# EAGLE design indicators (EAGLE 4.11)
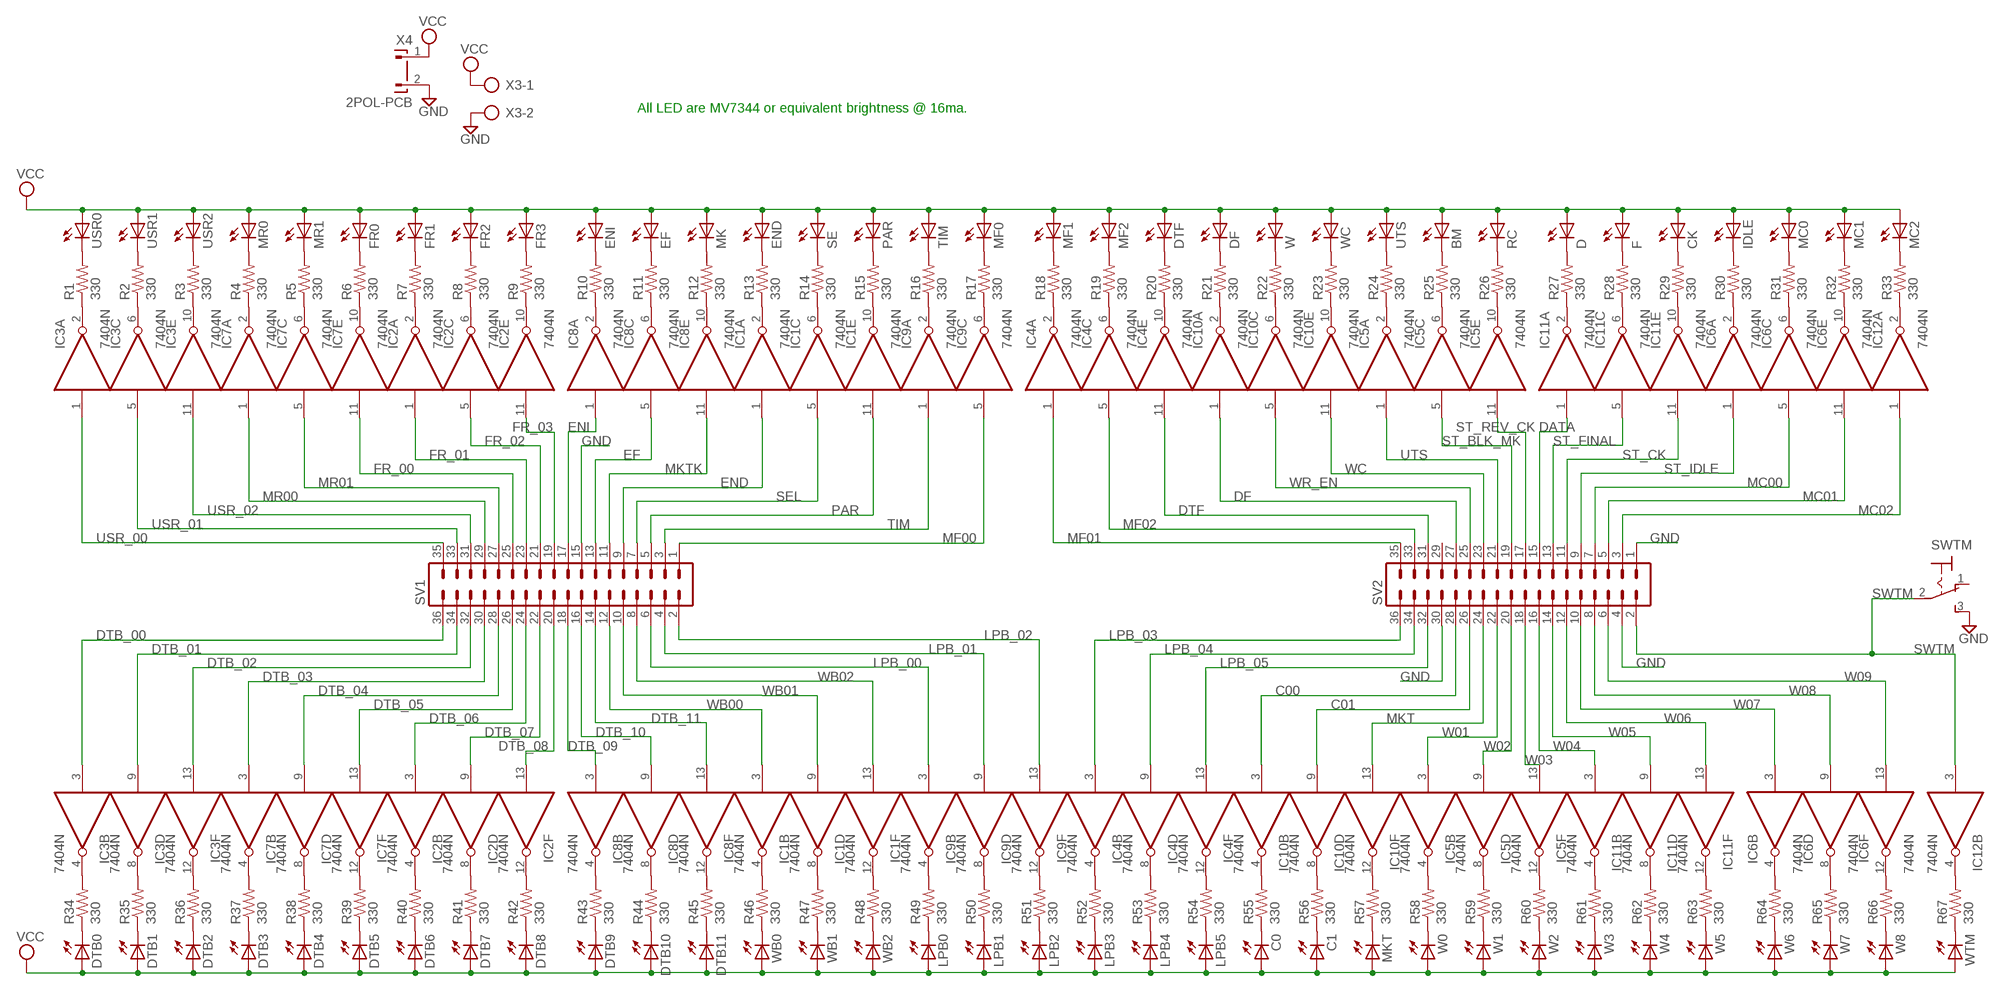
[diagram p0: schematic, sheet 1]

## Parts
BM  LED5MM  [LED5MM]
C0  LED5MM  [LED5MM]
C1  LED5MM  [LED5MM]
CK  LED5MM  [LED5MM]
D  LED5MM  [LED5MM]
DF  LED5MM  [LED5MM]
DTB0  LED5MM  [LED5MM]
DTB1  LED5MM  [LED5MM]
DTB2  LED5MM  [LED5MM]
DTB3  LED5MM  [LED5MM]
DTB4  LED5MM  [LED5MM]
DTB5  LED5MM  [LED5MM]
DTB6  LED5MM  [LED5MM]
DTB7  LED5MM  [LED5MM]
DTB8  LED5MM  [LED5MM]
DTB9  LED5MM  [LED5MM]
DTB10  LED5MM  [LED5MM]
DTB11  LED5MM  [LED5MM]
DTF  LED5MM  [LED5MM]
EF  LED5MM  [LED5MM]
END  LED5MM  [LED5MM]
ENI  LED5MM  [LED5MM]
F  LED5MM  [LED5MM]
FR0  LED5MM  [LED5MM]
FR1  LED5MM  [LED5MM]
FR2  LED5MM  [LED5MM]
FR3  LED5MM  [LED5MM]
IC1  7404N  [DIL14]
IC2  7404N  [DIL14]
IC3  7404N  [DIL14]
IC4  7404N  [DIL14]
IC5  7404N  [DIL14]
IC6  7404N  [DIL14]
IC7  7404N  [DIL14]
IC8  7404N  [DIL14]
IC9  7404N  [DIL14]
IC10  7404N  [DIL14]
IC11  7404N  [DIL14]
IC12  7404N  [DIL14]
IDLE  LED5MM  [LED5MM]
LPB0  LED5MM  [LED5MM]
LPB1  LED5MM  [LED5MM]
LPB2  LED5MM  [LED5MM]
LPB3  LED5MM  [LED5MM]
LPB4  LED5MM  [LED5MM]
LPB5  LED5MM  [LED5MM]
MC0  LED5MM  [LED5MM]
MC1  LED5MM  [LED5MM]
MC2  LED5MM  [LED5MM]
MF0  LED5MM  [LED5MM]
MF1  LED5MM  [LED5MM]
MF2  LED5MM  [LED5MM]
MK  LED5MM  [LED5MM]
MKT  LED5MM  [LED5MM]
MR0  LED5MM  [LED5MM]
MR1  LED5MM  [LED5MM]
PAR  LED5MM  [LED5MM]
R1  330  R-US_0207/10  [0207/10]
R2  330  R-US_0207/10  [0207/10]
R3  330  R-US_0207/10  [0207/10]
R4  330  R-US_0207/10  [0207/10]
R5  330  R-US_0207/10  [0207/10]
R6  330  R-US_0207/10  [0207/10]
R7  330  R-US_0207/10  [0207/10]
R8  330  R-US_0207/10  [0207/10]
R9  330  R-US_0207/10  [0207/10]
R10  330  R-US_0207/10  [0207/10]
R11  330  R-US_0207/10  [0207/10]
R12  330  R-US_0207/10  [0207/10]
R13  330  R-US_0207/10  [0207/10]
R14  330  R-US_0207/10  [0207/10]
R15  330  R-US_0207/10  [0207/10]
R16  330  R-US_0207/10  [0207/10]
R17  330  R-US_0207/10  [0207/10]
R18  330  R-US_0207/10  [0207/10]
R19  330  R-US_0207/10  [0207/10]
R20  330  R-US_0207/10  [0207/10]
R21  330  R-US_0207/10  [0207/10]
R22  330  R-US_0207/10  [0207/10]
R23  330  R-US_0207/10  [0207/10]
R24  330  R-US_0207/10  [0207/10]
R25  330  R-US_0207/10  [0207/10]
R26  330  R-US_0207/10  [0207/10]
R27  330  R-US_0207/10  [0207/10]
R28  330  R-US_0207/10  [0207/10]
R29  330  R-US_0207/10  [0207/10]
R30  330  R-US_0207/10  [0207/10]
R31  330  R-US_0207/10  [0207/10]
R32  330  R-US_0207/10  [0207/10]
R33  330  R-US_0207/10  [0207/10]
R34  330  R-US_0207/10  [0207/10]
R35  330  R-US_0207/10  [0207/10]
R36  330  R-US_0207/10  [0207/10]
R37  330  R-US_0207/10  [0207/10]
R38  330  R-US_0207/10  [0207/10]
R39  330  R-US_0207/10  [0207/10]
R40  330  R-US_0207/10  [0207/10]
R41  330  R-US_0207/10  [0207/10]
R42  330  R-US_0207/10  [0207/10]
R43  330  R-US_0207/10  [0207/10]
R44  330  R-US_0207/10  [0207/10]
R45  330  R-US_0207/10  [0207/10]
R46  330  R-US_0207/10  [0207/10]
R47  330  R-US_0207/10  [0207/10]
R48  330  R-US_0207/10  [0207/10]
R49  330  R-US_0207/10  [0207/10]
R50  330  R-US_0207/10  [0207/10]
R51  330  R-US_0207/10  [0207/10]
R52  330  R-US_0207/10  [0207/10]
R53  330  R-US_0207/10  [0207/10]
R54  330  R-US_0207/10  [0207/10]
R55  330  R-US_0207/10  [0207/10]
R56  330  R-US_0207/10  [0207/10]
R57  330  R-US_0207/10  [0207/10]
R58  330  R-US_0207/10  [0207/10]
R59  330  R-US_0207/10  [0207/10]
R60  330  R-US_0207/10  [0207/10]
R61  330  R-US_0207/10  [0207/10]
R62  330  R-US_0207/10  [0207/10]
R63  330  R-US_0207/10  [0207/10]
R64  330  R-US_0207/10  [0207/10]
R65  330  R-US_0207/10  [0207/10]
R66  330  R-US_0207/10  [0207/10]
R67  330  R-US_0207/10  [0207/10]
RC  LED5MM  [LED5MM]
SE  LED5MM  [LED5MM]
SV1  MA18-2  [MA18-2]
SV2  MA18-2  [MA18-2]
SWTM  M9040P  [M9040P]
TIM  LED5MM  [LED5MM]
USR0  LED5MM  [LED5MM]
USR1  LED5MM  [LED5MM]
USR2  LED5MM  [LED5MM]
UTS  LED5MM  [LED5MM]
W  LED5MM  [LED5MM]
W0  LED5MM  [LED5MM]
W1  LED5MM  [LED5MM]
W2  LED5MM  [LED5MM]
W3  LED5MM  [LED5MM]
W4  LED5MM  [LED5MM]
W5  LED5MM  [LED5MM]
W6  LED5MM  [LED5MM]
W7  LED5MM  [LED5MM]
W8  LED5MM  [LED5MM]
WB0  LED5MM  [LED5MM]
WB1  LED5MM  [LED5MM]
WB2  LED5MM  [LED5MM]
WC  LED5MM  [LED5MM]
WTM  LED5MM  [LED5MM]
X3  AK300/2  [AK300/2]
X4  2POL-PCB  [2POL-PCB]

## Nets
C00: IC10.3(B:I) SV2.28
C01: IC10.9(D:I) SV2.26
DATA: IC11.1(A:I) SV2.15
DF: IC10.1(A:I) SV2.27
DTB_00: IC3.3(B:I) SV1.36
DTB_01: IC3.9(D:I) SV1.34
DTB_02: IC3.13(F:I) SV1.32
DTB_03: IC7.3(B:I) SV1.30
DTB_04: IC7.9(D:I) SV1.28
DTB_05: IC7.13(F:I) SV1.26
DTB_06: IC2.3(B:I) SV1.24
DTB_07: IC2.9(D:I) SV1.22
DTB_08: IC2.13(F:I) SV1.20
DTB_09: IC8.3(B:I) SV1.18
DTB_10: IC8.9(D:I) SV1.16
DTB_11: IC8.13(F:I) SV1.14
DTF: IC4.11(E:I) SV2.31
EF: IC8.5(C:I) SV1.13
END: IC1.1(A:I) SV1.9
ENI: IC8.1(A:I) SV1.17
FR_00: IC7.11(E:I) SV1.25
FR_01: IC2.1(A:I) SV1.23
FR_02: IC2.5(C:I) SV1.21
FR_03: IC2.11(E:I) SV1.19
GND: SV1.15 SV2.1 SV2.4 SV2.30 SWTM.3(S) X3.2 X4.2
LPB_00: IC9.3(B:I) SV1.6
LPB_01: IC9.9(D:I) SV1.4
LPB_02: IC9.13(F:I) SV1.2
LPB_03: IC4.3(B:I) SV2.36
LPB_04: IC4.9(D:I) SV2.34
LPB_05: IC4.13(F:I) SV2.32
MC00: IC6.5(C:I) SV2.7
MC01: IC6.11(E:I) SV2.5
MC02: IC12.1(A:I) SV2.3
MF00: IC9.5(C:I) SV1.1
MF01: IC4.1(A:I) SV2.35
MF02: IC4.5(C:I) SV2.33
MKT: IC10.13(F:I) SV2.24
MKTK: IC8.11(E:I) SV1.11
MR00: IC7.1(A:I) SV1.29
MR01: IC7.5(C:I) SV1.27
N$1: R1.2 USR0.K(C)
N$2: R2.2 USR1.K(C)
N$3: R3.2 USR2.K(C)
N$4: MR0.K(C) R4.2
N$5: MR1.K(C) R5.2
N$6: FR0.K(C) R6.2
N$7: FR1.K(C) R7.2
N$8: FR2.K(C) R8.2
N$9: FR3.K(C) R9.2
N$10: ENI.K(C) R10.2
N$11: EF.K(C) R11.2
N$12: MK.K(C) R12.2
N$13: END.K(C) R13.2
N$14: R14.2 SE.K(C)
N$15: PAR.K(C) R15.2
N$16: R16.2 TIM.K(C)
N$17: MF0.K(C) R17.2
N$18: MF1.K(C) R18.2
N$19: MF2.K(C) R19.2
N$20: IC3.2(A:O) R1.1
N$21: IC3.6(C:O) R2.1
N$22: IC3.10(E:O) R3.1
N$23: IC7.2(A:O) R4.1
N$24: IC7.6(C:O) R5.1
N$25: IC7.10(E:O) R6.1
N$26: IC2.2(A:O) R7.1
N$27: IC2.6(C:O) R8.1
N$28: IC2.10(E:O) R9.1
N$29: IC8.2(A:O) R10.1
N$30: IC8.6(C:O) R11.1
N$31: IC8.10(E:O) R12.1
N$32: IC1.2(A:O) R13.1
N$33: IC1.6(C:O) R14.1
N$34: IC1.10(E:O) R15.1
N$35: IC9.2(A:O) R16.1
N$36: IC9.6(C:O) R17.1
N$37: IC4.2(A:O) R18.1
N$38: DTF.K(C) R20.2
N$57: DF.K(C) R21.2
N$58: R22.2 W.K(C)
N$59: R23.2 WC.K(C)
N$60: R24.2 UTS.K(C)
N$61: BM.K(C) R25.2
N$62: R26.2 RC.K(C)
N$63: D.K(C) R27.2
N$64: F.K(C) R28.2
N$65: CK.K(C) R29.2
N$66: IDLE.K(C) R30.2
N$67: MC0.K(C) R31.2
N$68: MC1.K(C) R32.2
N$69: MC2.K(C) R33.2
N$70: IC4.6(C:O) R19.1
N$71: IC4.10(E:O) R20.1
N$72: IC10.2(A:O) R21.1
N$73: IC10.10(E:O) R23.1
N$74: IC10.6(C:O) R22.1
N$75: IC5.2(A:O) R24.1
N$76: IC5.6(C:O) R25.1
N$77: IC5.10(E:O) R26.1
N$78: IC11.2(A:O) R27.1
N$79: IC11.6(C:O) R28.1
N$80: IC11.10(E:O) R29.1
N$81: IC6.2(A:O) R30.1
N$82: IC6.6(C:O) R31.1
N$83: IC6.10(E:O) R32.1
N$84: IC12.2(A:O) R33.1
N$89: DTB0.K(C) R34.1
N$90: DTB1.K(C) R35.1
N$91: DTB2.K(C) R36.1
N$92: DTB3.K(C) R37.1
N$93: DTB4.K(C) R38.1
N$94: DTB5.K(C) R39.1
N$95: DTB6.K(C) R40.1
N$96: DTB7.K(C) R41.1
N$97: DTB8.K(C) R42.1
N$98: DTB9.K(C) R43.1
N$99: DTB10.K(C) R44.1
N$100: DTB11.K(C) R45.1
N$101: R46.1 WB0.K(C)
N$102: R47.1 WB1.K(C)
N$103: R48.1 WB2.K(C)
N$104: LPB0.K(C) R49.1
N$105: LPB1.K(C) R50.1
N$106: LPB2.K(C) R51.1
N$107: LPB3.K(C) R52.1
N$108: LPB4.K(C) R53.1
N$109: LPB5.K(C) R54.1
N$110: C0.K(C) R55.1
N$111: C1.K(C) R56.1
N$112: MKT.K(C) R57.1
N$113: R58.1 W0.K(C)
N$114: R59.1 W1.K(C)
N$115: R60.1 W2.K(C)
N$116: R61.1 W3.K(C)
N$117: R62.1 W4.K(C)
N$118: R63.1 W5.K(C)
N$119: R64.1 W6.K(C)
N$120: R65.1 W7.K(C)
N$121: R66.1 W8.K(C)
N$122: R67.1 WTM.K(C)
N$123: IC3.4(B:O) R34.2
N$124: IC3.8(D:O) R35.2
N$125: IC3.12(F:O) R36.2
N$126: IC7.4(B:O) R37.2
N$127: IC7.8(D:O) R38.2
N$128: IC7.12(F:O) R39.2
N$129: IC2.4(B:O) R40.2
N$130: IC2.8(D:O) R41.2
N$131: IC2.12(F:O) R42.2
N$132: IC8.4(B:O) R43.2
N$133: IC8.8(D:O) R44.2
N$134: IC8.12(F:O) R45.2
N$135: IC1.4(B:O) R46.2
N$136: IC1.8(D:O) R47.2
N$137: IC1.12(F:O) R48.2
N$138: IC9.4(B:O) R49.2
N$139: IC9.8(D:O) R50.2
N$140: IC9.12(F:O) R51.2
N$141: IC4.4(B:O) R52.2
N$142: IC4.8(D:O) R53.2
N$143: IC4.12(F:O) R54.2
N$144: IC10.4(B:O) R55.2
N$145: IC10.8(D:O) R56.2
N$146: IC10.12(F:O) R57.2
N$147: IC5.4(B:O) R58.2
N$148: IC5.8(D:O) R59.2
N$149: IC5.12(F:O) R60.2
N$150: IC11.4(B:O) R61.2
N$151: IC11.8(D:O) R62.2
N$152: IC11.12(F:O) R63.2
N$153: IC6.4(B:O) R64.2
N$154: IC6.8(D:O) R65.2
N$155: IC6.12(F:O) R66.2
N$190: IC12.4(B:O) R67.2
PAR: IC1.11(E:I) SV1.5
SEL: IC1.5(C:I) SV1.7
ST_BLK_MK: IC5.5(C:I) SV2.19
ST_CK: IC11.11(E:I) SV2.11
ST_FINAL: IC11.5(C:I) SV2.13
ST_IDLE: IC6.1(A:I) SV2.9
ST_REV_CK: IC5.11(E:I) SV2.17
SWTM: IC12.3(B:I) SV2.2 SWTM.2(P)
TIM: IC9.1(A:I) SV1.3
USR_00: IC3.1(A:I) SV1.35
USR_01: IC3.5(C:I) SV1.33
USR_02: IC3.11(E:I) SV1.31
UTS: IC5.1(A:I) SV2.21
VCC: BM.A C0.A C1.A CK.A D.A DF.A DTB0.A DTB1.A DTB2.A DTB3.A DTB4.A DTB5.A DTB6.A DTB7.A DTB8.A DTB9.A DTB10.A DTB11.A DTF.A EF.A END.A ENI.A F.A FR0.A FR1.A FR2.A FR3.A IDLE.A LPB0.A LPB1.A LPB2.A LPB3.A LPB4.A LPB5.A MC0.A MC1.A MC2.A MF0.A MF1.A MF2.A MK.A MKT.A MR0.A MR1.A PAR.A RC.A SE.A TIM.A USR0.A USR1.A USR2.A UTS.A W0.A W1.A W2.A W3.A W4.A W5.A W6.A W7.A W8.A W.A WB0.A WB1.A WB2.A WC.A WTM.A X3.1 X4.1
W01: IC5.3(B:I) SV2.22
W02: IC5.9(D:I) SV2.20
W03: IC5.13(F:I) SV2.18
W04: IC11.3(B:I) SV2.16
W05: IC11.9(D:I) SV2.14
W06: IC11.13(F:I) SV2.12
W07: IC6.3(B:I) SV2.10
W08: IC6.9(D:I) SV2.8
W09: IC6.13(F:I) SV2.6
WB00: IC1.3(B:I) SV1.12
WB01: IC1.9(D:I) SV1.10
WB02: IC1.13(F:I) SV1.8
WC: IC10.11(E:I) SV2.23
WR_EN: IC10.5(C:I) SV2.25
Unconnected: IC9.10(E:O) IC9.11(E:I) IC12.5(C:I) IC12.6(C:O) IC12.8(D:O) IC12.9(D:I) IC12.10(E:O) IC12.11(E:I) IC12.12(F:O) IC12.13(F:I) SV2.29 SWTM.1(O)

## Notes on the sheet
- All LED are MV7344 or equivalent brightness @ 16ma.

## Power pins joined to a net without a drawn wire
GND: IC1.7(P:GND) IC2.7(P:GND) IC3.7(P:GND) IC4.7(P:GND) IC5.7(P:GND) IC6.7(P:GND) IC7.7(P:GND) IC8.7(P:GND) IC9.7(P:GND) IC10.7(P:GND) IC11.7(P:GND) IC12.7(P:GND)
VCC: IC1.14(P:VCC) IC2.14(P:VCC) IC3.14(P:VCC) IC4.14(P:VCC) IC5.14(P:VCC) IC6.14(P:VCC) IC7.14(P:VCC) IC8.14(P:VCC) IC9.14(P:VCC) IC10.14(P:VCC) IC11.14(P:VCC) IC12.14(P:VCC)

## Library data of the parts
BM C0 C1 CK D DF DTB0 DTB1-DTB11 DTF EF END ENI F FR0 FR1-FR3 IDLE LPB0 LPB1-LPB5 MC0 MC1 MC2 MF0 MF1 MF2 MK MKT MR0 MR1 PAR RC SE TIM USR0 USR1 USR2 UTS W W0 W1-W8 WB0 WB1 WB2 WC WTM = led:LED: LED
IC1-IC12 = 74xx-us:74*04: Hex INVERTER
R1-R67 = rcl:R-US_: RESISTOR, American symbol
SV1 SV2 = con-lstb:MA18-2: PIN HEADER
SWTM = switch:M9040P: TOGGLE SWITCH Marquardt
X3 = con-ptr500:AK300/2: CONNECTOR
X4 = con-friwo:2POL-PCB: PCB SUPPLY CONNECTOR

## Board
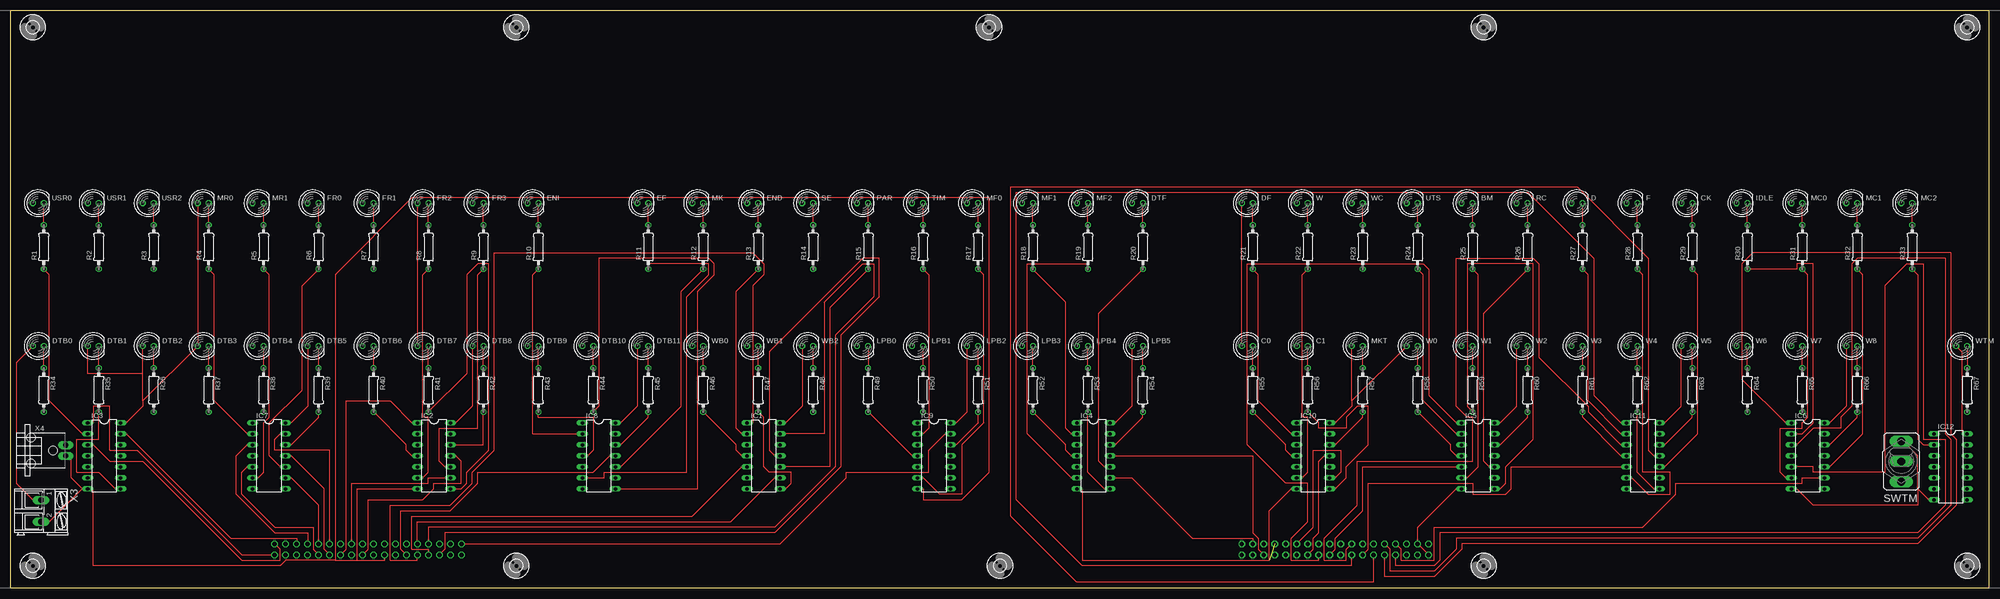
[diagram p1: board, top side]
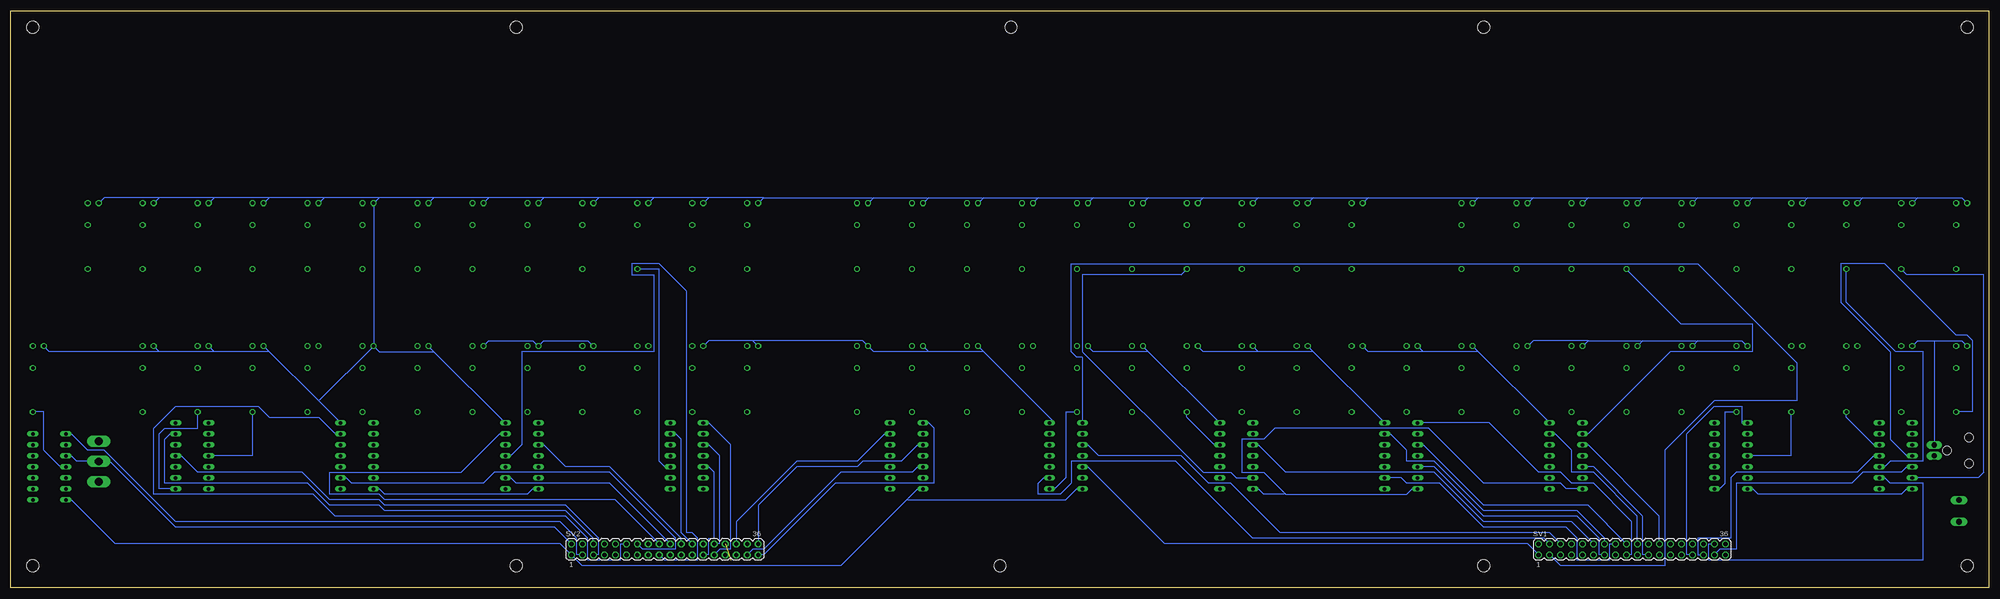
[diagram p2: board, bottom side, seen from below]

Size 457.2 x 133.35 mm. Coordinates in mm from the lower left corner, seen from the top.
Outline: 0,0 457.2,0 457.2,133.35 0,133.35 0,0
Copper layers (1*16): Top 0.035mm / dielectric 1.5mm / Bottom 0.035mm
Design rules "default": minimum track width 10mil, minimum drill 24mil, track to track 8mil, track to pad 8mil, pad to pad 8mil, via to via 8mil, smd to smd 8mil, copper to edge 40mil, drill to drill 8mil, minimum pad ring 10mil, minimum via ring 8mil, stop-mask expansion 4mil, vias tented up to drill 0mil, thermal gap 10mil

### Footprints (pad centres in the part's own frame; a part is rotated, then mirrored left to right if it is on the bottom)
LED5MM = drill 0.813 octagon: A -1.27,0; K 1.27,0
DIL14 = drill 0.813 long: 1 -7.62,-3.81; 2 -5.08,-3.81; 3 -2.54,-3.81; 4 0,-3.81; 5 2.54,-3.81; 6 5.08,-3.81; 7 7.62,-3.81; 8 7.62,3.81; 9 5.08,3.81; 10 2.54,3.81; 11 0,3.81; 12 -2.54,3.81; 13 -5.08,3.81; 14 -7.62,3.81
0207/10 = drill 0.813 octagon: 1 -5.08,0; 2 5.08,0
MA18-2 = drill 1.016 octagon: 1 -21.59,-1.27; 2 -21.59,1.27; 3 -19.05,-1.27; 4 -19.05,1.27; 5 -16.51,-1.27; 6 -16.51,1.27; 7 -13.97,-1.27; 8 -13.97,1.27; 9 -11.43,-1.27; 10 -11.43,1.27; 11 -8.89,-1.27; 12 -8.89,1.27; 13 -6.35,-1.27; 14 -6.35,1.27; 15 -3.81,-1.27; 16 -3.81,1.27; 17 -1.27,-1.27; 18 -1.27,1.27; 19 1.27,-1.27; 20 1.27,1.27; 21 3.81,-1.27; 22 3.81,1.27; 23 6.35,-1.27; 24 6.35,1.27; 25 8.89,-1.27; 26 8.89,1.27; 27 11.43,-1.27; 28 11.43,1.27; 29 13.97,-1.27; 30 13.97,1.27; 31 16.51,-1.27; 32 16.51,1.27; 33 19.05,-1.27; 34 19.05,1.27; 35 21.59,-1.27; 36 21.59,1.27
M9040P = drill 1.803 long: 1 0,4.699; 2 0,0; 3 0,-4.699
2,8 = hole 2.8: 0,0
AK300/2 = drill 1.321 long: 1 -2.515,0; 2 2.489,0
2POL-PCB = drill 1.2 long: 1 -1.25,11.6; 2 1.25,11.6 | hole 2: -3,3.6; 3,3.6; 0,8.6

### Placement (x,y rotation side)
BM  336.55,88.9 0 top
C0  285.75,55.88 0 top
C1  298.45,55.88 0 top
CK  387.35,88.9 0 top
D  361.95,88.9 0 top
DF  285.75,88.9 0 top
DTB0  6.35,55.88 0 top
DTB1  19.05,55.88 0 top
DTB2  31.75,55.88 0 top
DTB3  44.45,55.88 0 top
DTB4  57.15,55.88 0 top
DTB5  69.85,55.88 0 top
DTB6  82.55,55.88 0 top
DTB7  95.25,55.88 0 top
DTB8  107.95,55.88 0 top
DTB9  120.65,55.88 0 top
DTB10  133.35,55.88 0 top
DTB11  146.05,55.88 0 top
DTF  260.35,88.9 0 top
EF  146.05,88.9 0 top
END  171.45,88.9 0 top
ENI  120.65,88.9 0 top
F  374.65,88.9 0 top
FR0  69.85,88.9 0 top
FR1  82.55,88.9 0 top
FR2  95.25,88.9 0 top
FR3  107.95,88.9 0 top
IC1  173.99,30.48 270 top
IC2  97.79,30.48 270 top
IC3  21.59,30.48 270 top
IC4  250.19,30.48 270 top
IC5  339.09,30.48 270 top
IC6  415.29,30.48 270 top
IC7  59.69,30.48 270 top
IC8  135.89,30.48 270 top
IC9  213.36,30.48 270 top
IC10  300.99,30.48 270 top
IC11  377.19,30.48 270 top
IC12  448.31,27.94 270 top
IDLE  400.05,88.9 0 top
LPB0  196.85,55.88 0 top
LPB1  209.55,55.88 0 top
LPB2  222.25,55.88 0 top
LPB3  234.95,55.88 0 top
LPB4  247.65,55.88 0 top
LPB5  260.35,55.88 0 top
MC0  412.75,88.9 0 top
MC1  425.45,88.9 0 top
MC2  438.15,88.9 0 top
MF0  222.25,88.9 0 top
MF1  234.95,88.9 0 top
MF2  247.65,88.9 0 top
MK  158.75,88.9 0 top
MKT  311.15,55.88 0 top
MR0  44.45,88.9 0 top
MR1  57.15,88.9 0 top
PAR  196.85,88.9 0 top
R1  7.62,78.74 90 top
R2  20.32,78.74 90 top
R3  33.02,78.74 90 top
R4  45.72,78.74 90 top
R5  58.42,78.74 90 top
R6  71.12,78.74 90 top
R7  83.82,78.74 90 top
R8  96.52,78.74 90 top
R9  109.22,78.74 90 top
R10  121.92,78.74 90 top
R11  147.32,78.74 90 top
R12  160.02,78.74 90 top
R13  172.72,78.74 90 top
R14  185.42,78.74 90 top
R15  198.12,78.74 90 top
R16  210.82,78.74 90 top
R17  223.52,78.74 90 top
R18  236.22,78.74 90 top
R19  248.92,78.74 90 top
R20  261.62,78.74 90 top
R21  287.02,78.74 90 top
R22  299.72,78.74 90 top
R23  312.42,78.74 90 top
R24  325.12,78.74 90 top
R25  337.82,78.74 90 top
R26  350.52,78.74 90 top
R27  363.22,78.74 90 top
R28  375.92,78.74 90 top
R29  388.62,78.74 90 top
R30  401.32,78.74 90 top
R31  414.02,78.74 90 top
R32  426.72,78.74 90 top
R33  439.42,78.74 90 top
R34  7.62,45.72 270 top
R35  20.32,45.72 270 top
R36  33.02,45.72 270 top
R37  45.72,45.72 270 top
R38  58.42,45.72 270 top
R39  71.12,45.72 270 top
R40  83.82,45.72 270 top
R41  96.52,45.72 270 top
R42  109.22,45.72 270 top
R43  121.92,45.72 270 top
R44  134.62,45.72 270 top
R45  147.32,45.72 270 top
R46  160.02,45.72 270 top
R47  172.72,45.72 270 top
R48  185.42,45.72 270 top
R49  198.12,45.72 270 top
R50  210.82,45.72 270 top
R51  223.52,45.72 270 top
R52  236.22,45.72 270 top
R53  248.92,45.72 270 top
R54  261.62,45.72 270 top
R55  287.02,45.72 270 top
R56  299.72,45.72 270 top
R57  312.42,45.72 270 top
R58  325.12,45.72 270 top
R59  337.82,45.72 270 top
R60  350.52,45.72 270 top
R61  363.22,45.72 270 top
R62  375.92,45.72 270 top
R63  388.62,45.72 270 top
R64  401.32,45.72 270 top
R65  414.02,45.72 270 top
R66  426.72,45.72 270 top
R67  452.12,45.72 270 top
RC  349.25,88.9 0 top
SE  184.15,88.9 0 top
SV1  82.55,8.89 0 bottom
SV2  306.07,8.89 0 bottom
SWTM  436.88,29.21 180 top
TIM  209.55,88.9 0 top
U$1  [2,8]  5.08,5.08 0 top
U$2  [2,8]  5.08,129.54 0 top
U$3  [2,8]  116.84,5.08 0 top
U$4  [2,8]  116.84,129.54 0 top
U$5  [2,8]  226.06,129.54 0 top
U$6  [2,8]  228.6,5.08 0 top
U$7  [2,8]  340.36,129.54 0 top
U$8  [2,8]  340.36,5.08 0 top
U$9  [2,8]  452.12,129.54 0 top
U$10  [2,8]  452.12,5.08 0 top
USR0  6.35,88.9 0 top
USR1  19.05,88.9 0 top
USR2  31.75,88.9 0 top
UTS  323.85,88.9 0 top
W  298.45,88.9 0 top
W0  323.85,55.88 0 top
W1  336.55,55.88 0 top
W2  349.25,55.88 0 top
W3  361.95,55.88 0 top
W4  374.65,55.88 0 top
W5  387.35,55.88 0 top
W6  400.05,55.88 0 top
W7  412.75,55.88 0 top
W8  425.45,55.88 0 top
WB0  158.75,55.88 0 top
WB1  171.45,55.88 0 top
WB2  184.15,55.88 0 top
WC  311.15,88.9 0 top
WTM  450.85,55.88 0 top
X3  6.99,17.78 270 top
X4  1.11,31.75 270 top

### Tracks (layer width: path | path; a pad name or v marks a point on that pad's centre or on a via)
C00
  Bottom 0.254: SV2.28 293.37,10.16 293.37,30.48 295.91,33.02 IC10.3
C01
  Top 0.254: SV2.26 300.99,13.97 300.99,31.75 307.34,31.75 307.34,26.67 306.07,25.4 IC10.9
DATA
  Top 0.254: SV2.15 309.88,5.08 247.65,5.08 232.41,20.32 232.41,91.44 350.52,91.44 365.76,76.2 365.76,44.45 372.11,38.1 IC11.1
DF
  Bottom 0.254: SV2.27 293.37,8.89 290.83,8.89 290.83,33.02 295.91,38.1 IC10.1
DTB_00
  Top 0.254: SV1.36 62.23,8.89 62.23,6.35 53.34,6.35 30.48,29.21 22.86,29.21 19.05,33.02 IC3.3
DTB_01
  Bottom 0.254: SV1.34 64.77,10.16 64.77,6.35 15.24,6.35 15.24,24.13 22.86,24.13 24.13,25.4 IC3.9
DTB_02
  Top 0.254: SV1.32 66.04,11.43 50.8,11.43 26.67,35.56 IC3.13
DTB_03
  Top 0.254: SV1.30 68.58,12.7 60.96,12.7 52.07,21.59 52.07,30.48 54.61,33.02 IC7.3
DTB_04
  Top 0.254: SV1.28 71.12,19.05 64.77,25.4 IC7.9
DTB_05
  Top 0.254: SV1.26 73.66,31.75 60.96,31.75 60.96,34.29 62.23,35.56 IC7.13
DTB_06
  Bottom 0.254: SV1.24 76.2,16.51 92.71,33.02 IC2.3
DTB_07
  Top 0.254: SV1.22 78.74,24.13 96.52,24.13 96.52,25.4 100.33,25.4 IC2.9
DTB_08
  Bottom 0.254: SV1.20 81.28,16.51 91.44,26.67 96.52,26.67 96.52,31.75 100.33,35.56 IC2.13
DTB_09
  Bottom 0.254: SV1.18 92.71,19.05 116.84,19.05 130.81,33.02 IC8.3
DTB_10
  Bottom 0.254: SV1.16 87.63,10.16 87.63,6.35 95.25,6.35 95.25,11.43 97.79,13.97 116.84,13.97 127,24.13 134.62,24.13 135.89,25.4 138.43,25.4 IC8.9
DTB_11
  Bottom 0.254: SV1.14 88.9,11.43 95.25,17.78 116.84,17.78 128.27,29.21 134.62,29.21 134.62,31.75 138.43,35.56 IC8.13
DTF
  Top 0.254: SV2.31 288.29,8.89 288.29,11.43 287.02,12.7 287.02,30.48 255.27,30.48 IC4.11
EF
  Bottom 0.254: SV1.13 90.17,7.62 90.17,11.43 95.25,16.51 116.84,16.51 128.27,27.94 130.81,27.94 IC8.5
END
  Top 0.254: SV1.9 93.98,6.35 87.63,6.35 87.63,19.05 101.6,19.05 106.68,24.13 106.68,26.67 111.76,31.75 111.76,77.47 171.45,77.47 173.99,74.93 173.99,72.39 171.45,69.85 171.45,38.1 IC1.1
ENI
  Bottom 0.254: SV1.17 82.55,7.62 82.55,15.24 91.44,24.13 96.52,24.13 99.06,26.67 104.14,26.67 115.57,38.1 130.81,38.1 IC8.1
FR_00
  Top 0.254: SV1.25 72.39,8.89 72.39,22.86 64.77,30.48 IC7.11
FR_01
  Top 0.254: SV1.23 77.47,8.89 77.47,43.18 87.63,43.18 92.71,38.1 IC2.1
FR_02
  Bottom 0.254: SV1.21 80.01,7.62 80.01,16.51 91.44,27.94 92.71,27.94 IC2.5
FR_03
  Top 0.254: SV1.19 82.55,8.89 82.55,20.32 95.25,20.32 97.79,22.86 97.79,24.13 104.14,24.13 104.14,29.21 102.87,30.48 IC2.11
GND  (1 unrouted)
  Top 0.254: 440.69,22.86 443.23,20.32 IC12.7 | 440.69,22.86 440.69,30.48 438.15,33.02 SWTM.3 | 440.69,22.86 440.69,19.05 416.56,19.05 412.75,22.86 IC6.7 | IC5.7 334.01,22.86 325.12,13.97 SV2.4 SV2.1 | 80.01,6.35 80.01,22.86 92.71,22.86 IC2.7 | 80.01,6.35 86.36,6.35 SV1.15 | 16.51,22.86 13.97,25.4 13.97,30.48 X4.2 | IC3.7 16.51,22.86 | 16.51,22.86 8.89,15.24 X3.2 | IC3.7 16.51,22.86 | 74.93,6.35 63.5,6.35 62.23,5.08 19.05,5.08 19.05,22.86 IC3.7 | 74.93,6.35 80.01,6.35 | IC10.7 295.91,22.86 290.83,17.78 290.83,6.35 247.65,6.35 247.65,22.86 IC4.7 | 74.93,6.35 74.93,72.39 92.71,90.17 226.06,90.17 226.06,26.67 219.71,20.32 210.82,20.32 210.82,22.86 IC9.7
  Bottom 0.254: IC11.7 372.11,22.86 370.84,21.59 337.82,21.59 336.55,22.86 IC5.7 | IC12.7 443.23,20.32 433.07,10.16 330.2,10.16 SV2.1 325.12,5.08 265.43,5.08 250.19,20.32 | IC7.7 54.61,22.86 53.34,21.59 20.32,21.59 19.05,22.86 IC3.7 | 162.56,21.59 167.64,21.59 168.91,22.86 IC1.7 | 162.56,21.59 134.62,21.59 133.35,22.86 IC8.7 | 162.56,21.59 167.64,26.67 172.72,26.67 172.72,34.29 167.64,34.29 165.1,36.83 129.54,36.83 116.84,24.13 99.06,24.13 97.79,22.86 95.25,22.86 IC2.7 | 250.19,20.32 247.65,22.86 IC4.7 | 250.19,20.32 213.36,20.32 210.82,22.86 IC9.7
LPB_00
  Bottom 0.254: SV1.6 101.6,12.7 163.83,12.7 175.26,24.13 180.34,24.13 186.69,30.48 205.74,30.48 208.28,33.02 IC9.3
LPB_01
  Bottom 0.254: SV1.4 102.87,11.43 170.18,11.43 187.96,29.21 212.09,29.21 212.09,24.13 214.63,21.59 219.71,21.59 219.71,24.13 218.44,25.4 IC9.9
LPB_02
  Top 0.254: SV1.2 177.8,10.16 193.04,25.4 193.04,26.67 212.09,26.67 212.09,31.75 215.9,35.56 IC9.13
LPB_03
  Bottom 0.254: SV2.36 284.48,19.05 275.59,27.94 261.62,27.94 260.35,29.21 251.46,29.21 247.65,33.02 IC4.3
LPB_04
  Top 0.254: SV2.34 287.02,11.43 273.05,11.43 259.08,25.4 255.27,25.4 IC4.9
LPB_05
  Bottom 0.254: SV2.32 289.56,15.24 275.59,29.21 261.62,29.21 255.27,35.56 IC4.13
MC00
  Top 0.254: SV2.7 320.04,5.08 328.93,5.08 330.2,6.35 330.2,12.7 440.69,12.7 447.04,19.05 447.04,34.29 441.96,34.29 441.96,74.93 438.15,74.93 433.07,69.85 433.07,26.67 416.56,26.67 416.56,27.94 412.75,27.94 IC6.5
MC01
  Bottom 0.254: SV2.5 321.31,7.62 321.31,11.43 328.93,19.05 370.84,19.05 372.11,20.32 383.54,20.32 389.89,26.67 414.02,26.67 417.83,30.48 IC6.11
MC02
  Bottom 0.254: SV2.3 326.39,7.62 326.39,11.43 330.2,15.24 419.1,15.24 435.61,31.75 439.42,31.75 443.23,35.56 IC12.1
MF00
  Bottom 0.254: SV1.1 106.68,10.16 190.5,10.16 208.28,27.94 IC9.5
MF01
  Bottom 0.254: SV2.35 283.21,7.62 266.7,24.13 243.84,24.13 243.84,36.83 245.11,38.1 IC4.1
MF02
  Bottom 0.254: SV2.33 285.75,8.89 283.21,8.89 265.43,26.67 248.92,26.67 247.65,27.94 IC4.5
MKT
  Bottom 0.254: SV2.24 302.26,12.7 302.26,34.29 303.53,35.56 IC10.13
MKTK
  Top 0.254: SV1.11 90.17,8.89 90.17,17.78 101.6,17.78 107.95,24.13 107.95,26.67 134.62,26.67 138.43,30.48 IC8.11
MR00
  Bottom 0.254: SV1.29 69.85,7.62 69.85,35.56 63.5,41.91 57.15,41.91 57.15,38.1 IC7.1
MR01
  Top 0.254: SV1.27 69.85,8.89 69.85,13.97 60.96,13.97 53.34,21.59 53.34,26.67 54.61,27.94 IC7.5
N$1
  Top 0.254: R1.2 USR0.K
N$2
  Top 0.254: R2.2 USR1.K
N$3
  Top 0.254: R3.2 USR2.K
N$4
  Top 0.254: R4.2 MR0.K
N$5
  Top 0.254: R5.2 MR1.K
N$6
  Top 0.254: R6.2 FR0.K
N$7
  Top 0.254: R7.2 FR1.K
N$8
  Top 0.254: R8.2 FR2.K
N$9
  Top 0.254: R9.2 FR3.K
N$10
  Top 0.254: R10.2 ENI.K
N$11
  Top 0.254: R11.2 EF.K
N$12
  Top 0.254: R12.2 MK.K
N$13
  Top 0.254: R13.2 END.K
N$14
  Top 0.254: R14.2 SE.K
N$15
  Top 0.254: R15.2 PAR.K
N$16
  Top 0.254: R16.2 TIM.K
N$17
  Top 0.254: R17.2 MF0.K
N$18
  Top 0.254: R18.2 MF1.K
N$19
  Top 0.254: R19.2 MF2.K
N$20
  Top 0.254: R1.1 8.89,72.39 8.89,43.18 16.51,35.56 IC3.2
N$21
  Bottom 0.254: R2.1 19.05,72.39 1.27,72.39 1.27,26.67 2.54,25.4 16.51,25.4 IC3.6
N$22
  Bottom 0.254: R3.1 33.02,66.04 21.59,54.61 15.24,54.61 15.24,29.21 22.86,29.21 24.13,27.94 IC3.10
N$23
  Top 0.254: R4.1 46.99,72.39 46.99,43.18 54.61,35.56 IC7.2
N$24
  Top 0.254: R5.1 59.69,72.39 59.69,39.37 58.42,38.1 58.42,26.67 57.15,25.4 IC7.6
N$25
  Top 0.254: R6.1 67.31,69.85 67.31,45.72 59.69,38.1 59.69,30.48 62.23,27.94 IC7.10
N$26
  Bottom 0.254: R7.1 71.12,60.96 54.61,60.96 54.61,54.61 73.66,54.61 92.71,35.56 IC2.2
N$27
  Top 0.254: R8.1 95.25,72.39 95.25,39.37 96.52,39.37 96.52,26.67 95.25,25.4 IC2.6
N$28
  Top 0.254: R9.1 107.95,72.39 107.95,36.83 99.06,36.83 99.06,29.21 100.33,27.94 IC2.10
N$29
  Top 0.254: R10.1 120.65,72.39 120.65,35.56 130.81,35.56 IC8.2
N$30
  Top 0.254: R11.1 147.32,74.93 161.29,74.93 161.29,72.39 156.21,67.31 156.21,26.67 137.16,26.67 137.16,25.4 133.35,25.4 IC8.6
N$31
  Top 0.254: R12.1 154.94,68.58 154.94,41.91 140.97,27.94 IC8.10
N$32
  Top 0.254: R13.1 167.64,68.58 167.64,36.83 168.91,35.56 IC1.2
N$33
  Bottom 0.254: R14.1 186.69,72.39 209.55,72.39 209.55,54.61 181.61,26.67 175.26,26.67 173.99,25.4 171.45,25.4 IC1.6
N$34
  Top 0.254: R15.1 189.23,64.77 189.23,27.94 179.07,27.94 IC1.10
N$35
  Top 0.254: R16.1 212.09,72.39 212.09,36.83 210.82,35.56 IC9.2
N$36
  Top 0.254: R17.1 224.79,72.39 224.79,38.1 219.71,33.02 219.71,21.59 214.63,21.59 210.82,25.4 IC9.6
N$37
  Top 0.254: R18.1 243.84,66.04 243.84,36.83 245.11,35.56 IC4.2
N$38
  Top 0.254: R20.2 DTF.K
N$57
  Top 0.254: R21.2 DF.K
N$58
  Top 0.254: R22.2 W.K
N$59
  Top 0.254: R23.2 WC.K
N$60
  Top 0.254: R24.2 UTS.K
N$61
  Top 0.254: R25.2 BM.K
N$62
  Top 0.254: R26.2 RC.K
N$63
  Top 0.254: R27.2 D.K
N$64
  Top 0.254: R28.2 F.K
N$65
  Top 0.254: R29.2 CK.K
N$66
  Top 0.254: R30.2 IDLE.K
N$67
  Top 0.254: R31.2 MC0.K
N$68
  Top 0.254: R32.2 MC1.K
N$69
  Top 0.254: R33.2 MC2.K
N$70
  Top 0.254: R19.1 248.92,74.93 234.95,74.93 234.95,35.56 245.11,25.4 IC4.6
N$71
  Top 0.254: R20.1 251.46,63.5 251.46,29.21 252.73,27.94 IC4.10
N$72
  Top 0.254: R21.1 288.29,72.39 288.29,43.18 295.91,35.56 IC10.2
N$73
  Bottom 0.254: R23.1 307.34,73.66 307.34,29.21 306.07,27.94 IC10.10
N$74
  Top 0.254: R22.1 298.45,72.39 298.45,39.37 299.72,39.37 299.72,26.67 298.45,25.4 IC10.6
N$75
  Top 0.254: R24.1 326.39,72.39 326.39,43.18 334.01,35.56 IC5.2
N$76
  Top 0.254: R25.1 339.09,72.39 339.09,27.94 336.55,25.4 IC5.6
N$77
  Top 0.254: R26.1 340.36,63.5 340.36,29.21 341.63,27.94 IC5.10
N$78
  Top 0.254: R27.1 364.49,72.39 364.49,43.18 372.11,35.56 IC11.2
N$79
  Top 0.254: R28.1 377.19,72.39 377.19,26.67 383.54,26.67 383.54,21.59 378.46,21.59 374.65,25.4 IC11.6
N$80
  Top 0.254: R29.1 389.89,72.39 389.89,35.56 382.27,27.94 IC11.10
N$81
  Top 0.254: R30.1 412.75,73.66 412.75,74.93 416.56,74.93 416.56,38.1 414.02,35.56 412.75,35.56 IC6.2
N$82
  Top 0.254: R31.1 415.29,72.39 415.29,39.37 414.02,38.1 414.02,36.83 408.94,36.83 408.94,26.67 410.21,25.4 IC6.6
N$83
  Top 0.254: R32.1 427.99,72.39 427.99,35.56 420.37,27.94 IC6.10
N$84
  Top 0.254: R33.1 440.69,72.39 440.69,34.29 441.96,33.02 443.23,33.02 IC12.2
N$89
  Top 0.254: R34.1 DTB0.K
N$90
  Top 0.254: R35.1 DTB1.K
N$91
  Top 0.254: R36.1 DTB2.K
N$92
  Top 0.254: R37.1 DTB3.K
N$93
  Top 0.254: R38.1 DTB4.K
N$94
  Top 0.254: R39.1 DTB5.K
N$95
  Top 0.254: R40.1 DTB6.K
N$96
  Top 0.254: R41.1 DTB7.K
N$97
  Top 0.254: R42.1 DTB8.K
N$98
  Top 0.254: R43.1 DTB9.K
N$99
  Top 0.254: R44.1 DTB10.K
N$100
  Top 0.254: R45.1 DTB11.K
N$101
  Top 0.254: R46.1 WB0.K
N$102
  Top 0.254: R47.1 WB1.K
N$103
  Top 0.254: R48.1 WB2.K
N$104
  Top 0.254: LPB0.K R49.1
N$105
  Top 0.254: R50.1 LPB1.K
N$106
  Top 0.254: R51.1 LPB2.K
N$107
  Top 0.254: R52.1 LPB3.K
N$108
  Top 0.254: R53.1 LPB4.K
N$109
  Top 0.254: R54.1 LPB5.K
N$110
  Top 0.254: R55.1 C0.K
N$111
  Top 0.254: R56.1 C1.K
N$112
  Top 0.254: R57.1 MKT.K
N$113
  Top 0.254: R58.1 W0.K
N$114
  Top 0.254: R59.1 W1.K
N$115
  Top 0.254: R60.1 W2.K
N$116
  Top 0.254: R61.1 W3.K
N$117
  Top 0.254: R62.1 W4.K
N$118
  Top 0.254: R63.1 W5.K
N$119
  Top 0.254: R64.1 W6.K
N$120
  Top 0.254: R65.1 W7.K
N$121
  Top 0.254: R66.1 W8.K
N$122
  Top 0.254: WTM.K R67.1
N$123
  Bottom 0.254: R34.2 3.81,40.64 3.81,57.15 5.08,58.42 7.62,58.42 24.13,74.93 34.29,74.93 34.29,66.04 22.86,54.61 22.86,34.29 19.05,30.48 IC3.4
N$124
  Top 0.254: R35.2 20.32,34.29 15.24,34.29 15.24,26.67 20.32,26.67 24.13,22.86 IC3.8
N$125
  Bottom 0.254: R36.2 33.02,39.37 26.67,33.02 IC3.12
N$126
  Bottom 0.254: R37.2 45.72,30.48 54.61,30.48 IC7.4
N$127
  Bottom 0.254: R38.2 60.96,40.64 60.96,24.13 62.23,22.86 IC7.8
N$128
  Top 0.254: R39.2 71.12,39.37 64.77,33.02 IC7.12
N$129
  Top 0.254: R40.2 91.44,33.02 91.44,31.75 92.71,30.48 IC2.4
N$130
  Top 0.254: R41.2 105.41,49.53 105.41,72.39 107.95,74.93 110.49,74.93 110.49,31.75 105.41,26.67 105.41,24.13 104.14,22.86 102.87,22.86 IC2.8
N$131
  Top 0.254: R42.2 109.22,33.02 102.87,33.02 IC2.12
N$132
  Top 0.254: R43.2 121.92,39.37 134.62,39.37 134.62,31.75 133.35,30.48 IC8.4
N$133
  Top 0.254: R44.2 135.89,41.91 135.89,76.2 161.29,76.2 162.56,74.93 162.56,72.39 158.75,68.58 158.75,22.86 140.97,22.86 IC8.8
N$134
  Top 0.254: R45.2 147.32,39.37 140.97,33.02 IC8.12
N$135
  Top 0.254: R46.2 167.64,33.02 167.64,31.75 168.91,30.48 IC1.4
N$136
  Top 0.254: R47.2 173.99,39.37 173.99,27.94 175.26,26.67 180.34,26.67 180.34,24.13 179.07,22.86 IC1.8
N$137
  Bottom 0.254: R48.2 185.42,39.37 179.07,33.02 IC1.12
N$138
  Top 0.254: R49.2 208.28,30.48 IC9.4
N$139
  Bottom 0.254: R50.2 213.36,40.64 213.36,25.4 215.9,22.86 IC9.8
N$140
  Top 0.254: R51.2 223.52,38.1 218.44,33.02 IC9.12
N$141
  Top 0.254: R52.2 243.84,33.02 243.84,31.75 245.11,30.48 IC4.4
N$142
  Top 0.254: R53.2 248.92,26.67 252.73,22.86 IC4.8
N$143
  Top 0.254: R54.2 261.62,39.37 255.27,33.02 IC4.12
N$144
  Top 0.254: R55.2 294.64,33.02 294.64,31.75 295.91,30.48 IC10.4
N$145
  Top 0.254: R56.2 302.26,38.1 302.26,36.83 308.61,36.83 308.61,39.37 311.15,41.91 313.69,41.91 313.69,33.02 308.61,27.94 308.61,25.4 306.07,22.86 IC10.8
N$146
  Top 0.254: R57.2 312.42,39.37 306.07,33.02 IC10.12
N$147
  Top 0.254: R58.2 332.74,33.02 332.74,31.75 334.01,30.48 IC5.4
N$148
  Top 0.254: R59.2 336.55,41.91 336.55,74.93 351.79,74.93 351.79,34.29 345.44,27.94 345.44,24.13 344.17,22.86 IC5.8
N$149
  Top 0.254: R60.2 350.52,39.37 344.17,33.02 IC5.12
N$150
  Top 0.254: R61.2 363.22,39.37 372.11,30.48 IC11.4
N$151
  Top 0.254: R62.2 375.92,26.67 379.73,22.86 IC11.8
N$152
  Top 0.254: R63.2 388.62,39.37 382.27,33.02 IC11.12
N$153
  Bottom 0.254: R64.2 401.32,30.48 410.21,30.48 IC6.4
N$154
  Bottom 0.254: R65.2 414.02,36.83 421.64,36.83 422.91,35.56 422.91,22.86 420.37,22.86 IC6.8
N$155
  Top 0.254: R66.2 426.72,39.37 420.37,33.02 IC6.12
N$190
  Bottom 0.254: R67.2 449.58,40.64 449.58,31.75 445.77,27.94 IC12.4
PAR
  Top 0.254: SV1.5 100.33,8.89 100.33,12.7 176.53,12.7 191.77,27.94 191.77,58.42 200.66,67.31 200.66,76.2 196.85,76.2 175.26,54.61 175.26,31.75 176.53,30.48 IC1.11
SEL
  Top 0.254: SV1.7 96.52,8.89 92.71,8.89 92.71,16.51 157.48,16.51 168.91,27.94 IC1.5
ST_BLK_MK
  Top 0.254: SV2.19 306.07,8.89 306.07,11.43 312.42,17.78 312.42,27.94 334.01,27.94 IC5.5
ST_CK
  Top 0.254: SV2.11 314.96,1.27 246.38,1.27 231.14,16.51 231.14,92.71 361.95,92.71 378.46,76.2 378.46,31.75 379.73,30.48 IC11.11
ST_FINAL
  Top 0.254: SV2.13 313.69,8.89 313.69,24.13 337.82,24.13 337.82,21.59 345.44,21.59 346.71,22.86 346.71,27.94 372.11,27.94 IC11.5
ST_IDLE
  Top 0.254: SV2.9 317.5,2.54 328.93,2.54 335.28,8.89 335.28,10.16 440.69,10.16 449.58,19.05 449.58,34.29 448.31,35.56 448.31,77.47 402.59,77.47 400.05,74.93 400.05,48.26 410.21,38.1 IC6.1
ST_REV_CK
  Bottom 0.254: SV2.17 306.07,6.35 298.45,6.35 298.45,11.43 299.72,12.7 300.99,12.7 300.99,68.58 307.34,74.93 313.69,74.93 313.69,72.39 308.61,72.39 308.61,54.61 339.09,54.61 339.09,33.02 341.63,30.48 IC5.11
SWTM
  Bottom 0.254: IC12.3 443.23,30.48 441.96,29.21 439.42,29.21 SWTM.2 434.34,29.21 419.1,13.97 331.47,13.97 SV2.2
TIM
  Bottom 0.254: IC9.1 209.55,53.34 210.82,53.34 212.09,54.61 212.09,74.93 67.31,74.93 44.45,52.07 44.45,43.18 63.5,43.18 74.93,31.75 74.93,5.08 99.06,5.08 SV1.3
USR_00
  Top 0.254: SV1.35 53.34,7.62 29.21,31.75 22.86,31.75 22.86,41.91 19.05,41.91 19.05,38.1 IC3.1
USR_01
  Bottom 0.254: SV1.33 62.23,8.89 58.42,8.89 58.42,24.13 31.75,24.13 29.21,26.67 20.32,26.67 19.05,27.94 IC3.5
USR_02
  Bottom 0.254: SV1.31 67.31,7.62 67.31,11.43 59.69,11.43 59.69,25.4 58.42,26.67 30.48,26.67 26.67,30.48 IC3.11
UTS
  Top 0.254: SV2.21 302.26,6.35 295.91,6.35 295.91,11.43 299.72,15.24 299.72,24.13 294.64,24.13 285.75,33.02 285.75,74.93 326.39,74.93 327.66,73.66 327.66,44.45 334.01,38.1 IC5.1
VCC
  Top 0.254: WB2.A 182.88,41.91 179.07,38.1 IC1.14 | DTB11.A 144.78,41.91 140.97,38.1 IC8.14 | DTB8.A 106.68,41.91 102.87,38.1 IC2.14 | DTB5.A 68.58,41.91 64.77,38.1 IC7.14 | 309.88,43.18 MKT.A | 309.88,43.18 309.88,41.91 306.07,38.1 IC10.14 | W0.A 309.88,43.18 | W2.A 347.98,41.91 344.17,38.1 IC5.14 | WTM.A 450.85,54.61 450.85,35.56 IC12.14 | W8.A 424.18,41.91 420.37,38.1 IC6.14 | W5.A 386.08,41.91 382.27,38.1 IC11.14 | 30.48,49.53 DTB2.A | 30.48,43.18 30.48,49.53 | 30.48,43.18 30.48,41.91 26.67,38.1 IC3.14 | 30.48,43.18 DTB3.A MR0.A | DTB0.A 1.27,52.07 1.27,24.13 5.08,20.32 X3.1 | 30.48,49.53 17.78,49.53 DTB1.A | LPB5.A 259.08,41.91 255.27,38.1 IC4.14 | LPB2.A 220.98,40.64 218.44,38.1 IC9.14 | C0.A DF.A | FR2.A DTB7.A
  Bottom 0.254: IC1.14 194.31,54.61 | 194.31,54.61 LPB0.A | LPB1.A 207.01,54.61 194.31,54.61 | IC8.14 156.21,54.61 | 156.21,54.61 WB0.A | 168.91,54.61 WB1.A | 156.21,54.61 168.91,54.61 | IC2.14 118.11,54.61 | 118.11,54.61 DTB9.A | 130.81,54.61 DTB10.A | 118.11,54.61 130.81,54.61 | DTB4.A 57.15,57.15 67.31,57.15 | 67.31,57.15 DTB5.A | 80.01,57.15 DTB6.A | 80.01,57.15 67.31,57.15 | DTB7.A 92.71,57.15 | 92.71,57.15 80.01,57.15 | DTB8.A 105.41,57.15 92.71,57.15 | DTB11.A 143.51,54.61 130.81,54.61 | WB2.A 181.61,54.61 168.91,54.61 | W0.A 323.85,57.15 334.01,57.15 W1.A 336.55,57.15 346.71,57.15 W2.A | 359.41,54.61 IC5.14 | 359.41,54.61 W3.A | W4.A 372.11,54.61 359.41,54.61 | 386.08,43.18 IC11.14 | 386.08,43.18 397.51,54.61 | 397.51,54.61 W6.A | 410.21,54.61 W7.A | 397.51,54.61 410.21,54.61 | 422.91,54.61 W8.A | 410.21,54.61 422.91,54.61 | WTM.A 448.31,54.61 422.91,54.61 | W4.A 386.08,43.18 | DTB0.A 6.35,57.15 12.7,57.15 | 12.7,57.15 16.51,57.15 DTB1.A | 12.7,57.15 12.7,33.02 X4.1 | 232.41,54.61 215.9,38.1 IC9.14 | 232.41,54.61 LPB3.A | 245.11,54.61 LPB4.A | 232.41,54.61 245.11,54.61 | 245.11,54.61 257.81,54.61 LPB5.A 260.35,57.15 285.75,57.15 | 285.75,57.15 C0.A | 285.75,57.15 295.91,57.15 C1.A | USR0.A 6.35,90.17 16.51,90.17 | 16.51,90.17 USR1.A | 29.21,90.17 USR2.A | 29.21,90.17 16.51,90.17 | 41.91,90.17 MR0.A | 41.91,90.17 29.21,90.17 | 54.61,90.17 MR1.A | 54.61,90.17 41.91,90.17 | 67.31,90.17 FR0.A | 67.31,90.17 54.61,90.17 | 80.01,90.17 FR1.A | 80.01,90.17 67.31,90.17 | 92.71,90.17 FR2.A | 92.71,90.17 80.01,90.17 | 105.41,90.17 FR3.A | 105.41,90.17 92.71,90.17 | 118.11,90.17 ENI.A | 118.11,90.17 105.41,90.17 | 143.51,90.17 EF.A | 143.51,90.17 118.11,90.17 | 156.21,90.17 MK.A | 156.21,90.17 143.51,90.17
  Bottom 0.254: 168.91,90.17 END.A | 168.91,90.17 156.21,90.17 | 181.61,90.17 SE.A | 181.61,90.17 168.91,90.17 | 194.31,90.17 PAR.A | 194.31,90.17 181.61,90.17 | 207.01,90.17 TIM.A | 207.01,90.17 194.31,90.17 | 219.71,90.17 MF0.A | 219.71,90.17 207.01,90.17 | 232.41,90.17 MF1.A | 232.41,90.17 219.71,90.17 | 245.11,90.17 MF2.A | 245.11,90.17 232.41,90.17 | 257.81,90.17 DTF.A | 257.81,90.17 245.11,90.17 | DF.A 283.21,90.17 | 283.21,90.17 257.81,90.17 | 295.91,90.17 W.A | 283.21,90.17 295.91,90.17 | 308.61,90.17 WC.A | 295.91,90.17 308.61,90.17 | 321.31,90.17 UTS.A | 308.61,90.17 321.31,90.17 | 334.01,90.17 BM.A | 321.31,90.17 334.01,90.17 | 346.71,90.17 RC.A | 334.01,90.17 346.71,90.17 | 359.41,90.17 D.A | 346.71,90.17 359.41,90.17 | 372.11,90.17 F.A W4.A | 359.41,90.17 372.11,90.17 | 384.81,90.17 CK.A | 372.11,90.17 384.81,90.17 | 397.51,90.17 IDLE.A | 384.81,90.17 397.51,90.17 | 410.21,90.17 MC0.A | 397.51,90.17 410.21,90.17 | 422.91,90.17 MC1.A | 410.21,90.17 422.91,90.17 | MC2.A 435.61,90.17 422.91,90.17
W01
  Bottom 0.254: SV2.22 302.26,11.43 318.77,27.94 328.93,27.94 334.01,33.02 IC5.3
W02
  Bottom 0.254: SV2.20 318.77,24.13 340.36,24.13 341.63,25.4 IC5.9
W03
  Bottom 0.254: SV2.18 317.5,20.32 370.84,20.32 372.11,21.59 383.54,21.59 383.54,26.67 353.06,26.67 344.17,35.56 IC5.13
W04
  Top 0.254: SV2.16 308.61,8.89 308.61,6.35 303.53,6.35 303.53,11.43 311.15,19.05 311.15,29.21 337.82,29.21 337.82,39.37 336.55,39.37 334.01,41.91 334.01,76.2 351.79,76.2 353.06,74.93 353.06,53.34 364.49,41.91 364.49,40.64 372.11,33.02 IC11.3
W05
  Bottom 0.254: SV2.14 311.15,8.89 303.53,8.89 303.53,11.43 318.77,26.67 345.44,26.67 347.98,24.13 378.46,24.13 379.73,25.4 IC11.9
W06
  Bottom 0.254: SV2.12 316.23,10.16 316.23,6.35 323.85,6.35 323.85,11.43 328.93,16.51 382.27,16.51 387.35,21.59 424.18,21.59 424.18,36.83 419.1,41.91 400.05,41.91 397.51,39.37 386.08,39.37 382.27,35.56 IC11.13
W07
  Top 0.254: SV2.10 318.77,8.89 318.77,3.81 328.93,3.81 334.01,8.89 334.01,11.43 440.69,11.43 448.31,19.05 448.31,34.29 447.04,35.56 447.04,76.2 426.72,76.2 425.45,74.93 425.45,41.91 422.91,39.37 422.91,36.83 416.56,36.83 412.75,33.02 IC6.3
W08
  Top 0.254: SV2.8 321.31,8.89 321.31,6.35 328.93,6.35 328.93,13.97 377.19,13.97 384.81,21.59 384.81,24.13 414.02,24.13 414.02,25.4 417.83,25.4 IC6.9
W09
  Bottom 0.254: SV2.6 322.58,11.43 328.93,17.78 370.84,17.78 372.11,19.05 383.54,19.05 388.62,24.13 421.64,24.13 421.64,34.29 420.37,35.56 IC6.13
WB00
  Bottom 0.254: SV1.12 96.52,15.24 116.84,15.24 128.27,26.67 162.56,26.67 168.91,33.02 IC1.3
WB01
  Top 0.254: SV1.10 93.98,15.24 166.37,15.24 176.53,25.4 IC1.9
WB02
  Top 0.254: SV1.8 96.52,13.97 176.53,13.97 190.5,27.94 190.5,58.42 199.39,67.31 199.39,74.93 196.85,74.93 187.96,66.04 187.96,35.56 179.07,35.56 IC1.13
WC
  Top 0.254: SV2.23 300.99,8.89 300.99,11.43 302.26,12.7 302.26,29.21 303.53,30.48 IC10.11
WR_EN
  Bottom 0.254: SV2.25 295.91,7.62 295.91,11.43 294.64,11.43 294.64,26.67 295.91,27.94 IC10.5

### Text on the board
Document: USR | MR | FR | ENI | EF | MK | END | SE | PAR | TIM | MF | DTF | DF | W | UTS | STATE | WC | MC | 0 | 1 | 2 | 0 | 1 | 0 | 1 | 2 | 3 | 0 | 1 | 2 | BM | RC | D | F | CK | 0 | 1 | 2 | DTB | WB | LPB | C0 | C1 | MKT | WINDOW | WTM | 0 | 1 | 2 | 3 | 4 | 5 | 6 | 7 | 8 | 9 | 10 | 11 | 0 | 1 | 2 | 0 | 1 | 2 | 3 | 4 | 5 | 1 | 2 | 3 | 4 | 5 | 6 | 7 | 8 | 9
